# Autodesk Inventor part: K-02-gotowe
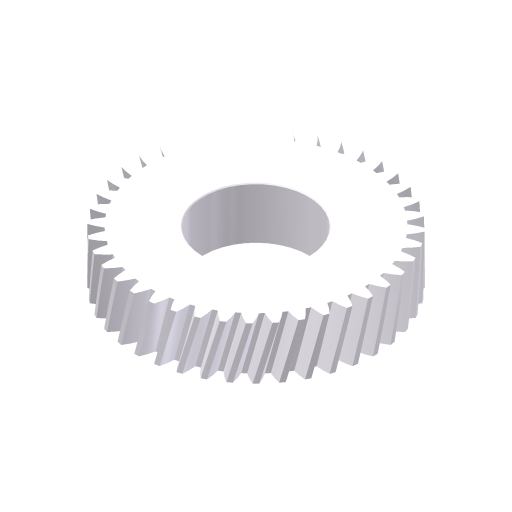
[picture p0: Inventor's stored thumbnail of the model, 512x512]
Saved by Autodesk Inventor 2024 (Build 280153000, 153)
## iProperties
Company: ATC
CustomPartVersion: 1
Created: 2023-03
Part Number: K-02-gotowe
Material: Stal kuta
Document SubType Name: Modeling
Designer: Andrzej Jaskulski
Categories: <?xml version="1.0" encoding="UTF-16"?> <MemberInstance><Categories><FamilyTemplate><FamilyTemplateParameter ValueType="xs:double" Id="1" ObjectReferenceKey="da
Density: 1 g/cm^3
Stock Number: K-02-gotowe
Appearance: Stal
Checked By: A.J.
Engr Approved By: Andrzej Jaskulski
Mfg Approved By: Andrzej Jaskulski
Authority: A.J.
Title: A.J.: Kurs R2024-MEP
Author: Andrzej Jaskulski
Revision Number: 1/24
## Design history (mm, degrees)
sketch "Sketch1"
  geometry: C1 r 114.325 at (0, 0)
  constraints: 1 centre point
  dimensions: "d0" = 228.64953 diameter of C1 (= da_da)
extrude "Extrusion1" new body sketch "Sketch1" distance "d1" = 50 (= da_b); taper "d2" = 0 deg
workplane "Work Plane2"
feature "Średnica podziałowa" dims "d4" = 10, "d5" = 0
workplane "Work Plane8"
workplane "Work Plane9"
feature "Przekładnia zębata czołowa" dims "da_b" = 50, "da_d" = 227.76076, "da_aw" = 180, "da_da" = 228.64953, "da_df" = 204.97857, "da_dw" = 221.53846, angle "da_beta" = 15 deg, "da_lefttooth" = 0, "da_righttooth" = 10
hole "Otwory1" diameter "d51" = 100; stored, may be unused: countersink angle "d55" = 90 deg, drill point angle "d57" = 118 deg; dims "d49" = 10, "d50" = 10, "d52" = 6, "d53" = 4, "d54" = 2, "d56" = 8
chamfer "Faza1" distance "d58" = 0.8; stored, may be unused: second distance "d59" = 2, angle "d60" = 45 deg
node "Bryła1"
node "Korpusy bryłowe"
node "Korpusy powierzchniowe"
sketch "Sketch2"
  geometry: C1 r 114.325 at (0, 0) reference; C2 r 110.769 at (0, 0)
  constraints: 1 centre point, 1 coincident
  dimensions: "d3" = 221.53846 diameter of C2 (= da_dw)
body "Srf1"
other parameters: "d17" = 0, "d34" = 4.5 deg (computed from da_z), "d39" = 0, "d41" = 0, "d47" = 0, "d48" = 0
